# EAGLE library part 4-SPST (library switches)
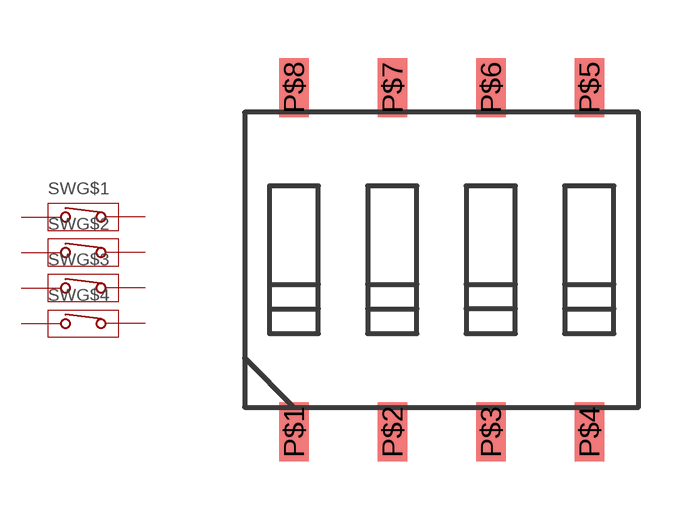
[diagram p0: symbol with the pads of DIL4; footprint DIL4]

Designator prefix SW; gates G$1=SPST G$2=SPST G$3=SPST G$4=SPST

## 4-SPSTSMD  [DIL4]
P$1  G$1:P1  pas
P$2  G$2:P1  pas
P$3  G$3:P1  pas
P$4  G$4:P1  pas
P$5  G$4:P2  pas
P$6  G$3:P2  pas
P$7  G$2:P2  pas
P$8  G$1:P2  pas

## Footprint DIL4 (pad centres in mm)
smd 0.762 x 1.524: P$1 -3.81,-4.445; P$2 -1.27,-4.445; P$3 1.27,-4.445; P$4 3.81,-4.445; P$5 3.81,4.445; P$6 1.27,4.445; P$7 -1.27,4.445; P$8 -3.81,4.445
